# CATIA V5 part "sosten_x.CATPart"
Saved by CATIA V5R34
Part number: Part3.1
Bounding box of the stored display mesh (mm): x -62 to 13, y -30 to 30, z -13 to 38
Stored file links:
  C:\Users\Apolinar\Desktop\cnc\sosten_x.CATPart
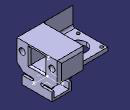
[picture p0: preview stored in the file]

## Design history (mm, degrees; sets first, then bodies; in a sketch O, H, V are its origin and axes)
AxisSystem1: origin (0, 0, 0), X (1, 0, 0), Y (0, 1, 0), Z (0, 0, 1)
Body1 (main body)
  Sketch1 on ZX plane of AxisSystem1, origin (0, 0, 0), H (0, 0, 1), V (1, 0, 0)
    line L1 (10, 10) -> (10, -10)
    line L2 (10, -10) -> (-10, -10)
    line L3 (-10, -10) -> (-10, 10)
    line L4 (-10, 10) -> (10, 10)
    line L5 (13, 13) -> (13, -13)
    line L6 (13, -13) -> (-13, -13)
    line L7 (-13, -13) -> (-13, 13)
    line L8 (-13, 13) -> (13, 13)
    length L1 = 20
    length L4 = 20
    distance L5 L1 = 3
    distance L2 L6 = 3
    vertical: L1 V, L3 V, L5 V, L7 V
    horizontal: L2 H, L4 H, L6 H, L8 H
    equidistance: L1 L3 O, L2 L4 O, L5 L7 O, L6 L8 O
  Pad1: profile Sketch1, direction (0, 1, 0), length 20, mirrored extent
  Sketch2 on face of Pad1 from Sketch1.L6, origin (-13, 0, 0), H (0, -1, 0), V (0, 0, 1)
    construction line L1 (-7, 0) -> (-20, 0)
    point P1 (-7, 0)
    point P2 (-20, 0)
    line L2 (-7, -2) -> (-20, -2)
    line L3 (-20, 2) -> (-7, 2)
    arc A1 centre (-20, 0) radius 2 from (-20, -2) to (-20, 2) cw
    arc A2 centre (-7, 0) radius 2 from (-7, 2) to (-7, -2) cw
    point P3 (-7, -2)
    point P4 (-20, -2)
    point P5 (-20, 2)
    point P6 (-7, 2)
    reference projected line E1 (-20, -13) -> (-20, 13) from edge [face of Pad1 from Sketch1.L6 | end face of Pad1]
    construction line L4 (7, 0) -> (20, 0)
    point P9 (7, -2)
    point P10 (20, -2)
    point P11 (20, 2)
    point P12 (7, 2)
    line L5 (7, -2) -> (20, -2)
    line L6 (20, 2) -> (7, 2)
    arc A3 centre (20, 0) radius 2 from (20, -2) to (20, 2) ccw
    arc A4 centre (7, 0) radius 2 from (7, 2) to (7, -2) ccw
    distance L1 L2 = 2
    distance A2 A4 = 10
    coincidence: P1 H, P2 E1
    horizontal: L1 H
    tangency: A1 L2, A2 L2, A1 L3, A2 L3
    symmetry: L1 L4 V, P3 P9 V, P4 P10 V, P5 P11 V, P6 P12 V, L2 L5 V, L3 L6 V, A1 A3 V, A2 A4 V
  Pocket1: profile Sketch2, direction (1, 0, 0), through (limit type 3)
  Sketch3 on face of Pad1 from Sketch1.L5, origin (0, 0, 13), H (1, 0, 0), V (0, 1, 0)
    point P1 (-4.5, 0)
    line L1 (13, 30) -> (13, -30)
    line L2 (13, -30) -> (-22, -30)
    line L3 (-22, -27) -> (-22, 30)
    line L4 (-22, 30) -> (13, 30)
    reference projected line E1 (13, -20) -> (13, 20) from edge [face of Pad1 from Sketch1.L8 | face of Pad1 from Sketch1.L5]
    line L5 (-22, -30) -> (-62, -30)
    line L6 (-62, -30) -> (-62, -27)
    line L7 (-62, -27) -> (-22, -27)
    length L1 = 60
    length L2 = 35
    length L6 = 3
    length L5 = 40
    length L4 = 35
    coincidence: P1 H, L1 E1
    vertical: L1 V, L3 V, L6 V
    horizontal: L2 H, L4 H, L5 H, L7 H
    equidistance: L1 L3 P1, L2 L4 P1
  Pad2: profile Sketch3, direction (0, 0, 1), length 25
  Sketch4 on face of Pad2, origin (13, 0, 0), H (0, 1, 0), V (0, 0, 1)
    circle A1 centre (-20, 25.5) radius 4
    point P1 (-20, 25.5)
    circle A2 centre (20, 25.5) radius 4
    reference projected line E1 (-30, 38) -> (30, 38) from edge [face of Pad2 from Sketch3.L1 | end face of Pad2]
    reference projected line E2 (-30, 13) -> (-30, 38) from edge [face of Pad2 from Sketch3.L1 | face of Pad2 from Sketch3.L2]
    radius A1 = 4
    distance P1 E1 = 12.5
    distance P1 E2 = 10
    symmetry: A1 A2 V
  Pocket2: profile Sketch4, direction (-1, 0, 0), length 10
  Sketch5 on face of Pad2, origin (13, 0, 0), H (0, 1, 0), V (0, 0, 1)
    point P1 (0, 24)
    line L1 (10, 34) -> (10, 14)
    line L2 (10, 14) -> (-10, 14)
    line L3 (-10, 14) -> (-10, 34)
    line L4 (-10, 34) -> (10, 34)
    reference projected line E1 (-30, 13) -> (30, 13) from edge [start face of Pad2 | face of Pad2]
    length L1 = 20
    length L4 = 20
    distance P1 E1 = 11
    coincidence: P1 V
    vertical: L1 V, L3 V
    horizontal: L2 H, L4 H
    equidistance: L1 L3 P1, L2 L4 P1
  Pocket3: profile Sketch5, direction (-1, 0, 0), through (limit type 6)
  Chamfer1: length 10, angle 45, on edge [start face of Pad1 | start face of Pad2]; edge [start face of Pad2 | end face of Pad1]
  Sketch6 on start face of Pad2, origin (0, 0, 13), H (1, 0, 0), V (0, -1, 0)
    line L1 (-62, 30) -> (-13, 30)
    line L2 (-13, 30) -> (-13, -20)
    line L3 (-13, -20) -> (-62, -20)
    line L4 (-62, -20) -> (-62, 30)
    reference projected line E1 (-62, 30) -> (-22, 30) from edge [start face of Pad2 | face of Pad2 from Sketch3.L5]
    reference projected line E2 (-62, 27) -> (-62, 30) from edge [start face of Pad2 | face of Pad2 from Sketch3.L6]
    reference projected line E3 (-13, -20) -> (-13, 20) from edge [face of Pad1 from Sketch1.L6 | start face of Pad2]
    circle A1 centre (-42, 0) radius 11.25
    point P5 (-42, 0)
    circle A2 centre (-58, -15.75) radius 2
    point P6 (-58, -15.75)
    construction line L5 (-42, 0) -> (-58.3956, 0)
    point P7 (-58.3956, 0)
    point P8 (-58, 15.75)
    circle A3 centre (-58, 15.75) radius 2
    axis line L6 (-42.25, -15.75) -> (-42.25, 15.75)
    point P12 (-26.1044, 0)
    point P13 (-26.5, 15.75)
    circle A4 centre (-26.5, -15.75) radius 2
    circle A5 centre (-26.5, 15.75) radius 2
    length L4 = 50
    radius A1 = 11.25
    distance P5 L4 = 20
    radius A2 = 2
    distance L4 A2 = 2
    distance P8 P6 = 31.5
    distance P8 P13 = 31.5
    horizontal: L1 H, L3 H, L5 H
    vertical: L2 V, L4 V, L6 V
    coincidence: L1 E1, E2 L4, L2 E3, P5 H
    symmetry: A2 A3 L5, P7 P12 L6, A2 A4 L6, A3 A5 L6
  Pad3: profile Sketch6, direction (0, 0, -1), length 5
  Chamfer2: length 3, angle 45, on edge [face of Pad3 | end face of Pad2]; edge [face of Pad2 | face of Pad3]; edge [face of Pad3 | end face of Pad3]; edge [face of Pad3 | face of Pad3 from Sketch6.L2]; edge [face of Pad3 | face of Pad3]
  Fillet1: radius 3, on edge [face of Pad2 from Sketch3.L7 | face of Pad2 from Sketch3.L3]; edge [start face of Pad3 | face of Pad2 from Sketch3.L7]
  Fillet2: radius 2, on edge [face of Pad2 from Sketch3.L3 | face of Pocket3 from Sketch5.L3]; edge [face of Pad2 from Sketch3.L3 | face of Pocket3 from Sketch5.L2]; edge [face of Pad2 from Sketch3.L3 | face of Pocket3 from Sketch5.L1]; edge [face of Pad2 from Sketch3.L3 | face of Pocket3 from Sketch5.L4]; edge [face of Pad2 | face of Pocket3 from Sketch5.L2]; edge [face of Pad2 | face of Pocket3 from Sketch5.L3]; edge [face of Pad2 | face of Pocket3 from Sketch5.L4]; edge [face of Pad2 | face of Pocket3 from Sketch5.L1]
  Chamfer3: length 3, angle 45, on edge [face of Pad2 from Sketch3.L4 | face of Pad2]; edge [face of Pad2 from Sketch3.L4 | end face of Pad2]; edge [face of Pad2 from Sketch3.L3 | face of Pad2 from Sketch3.L4]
